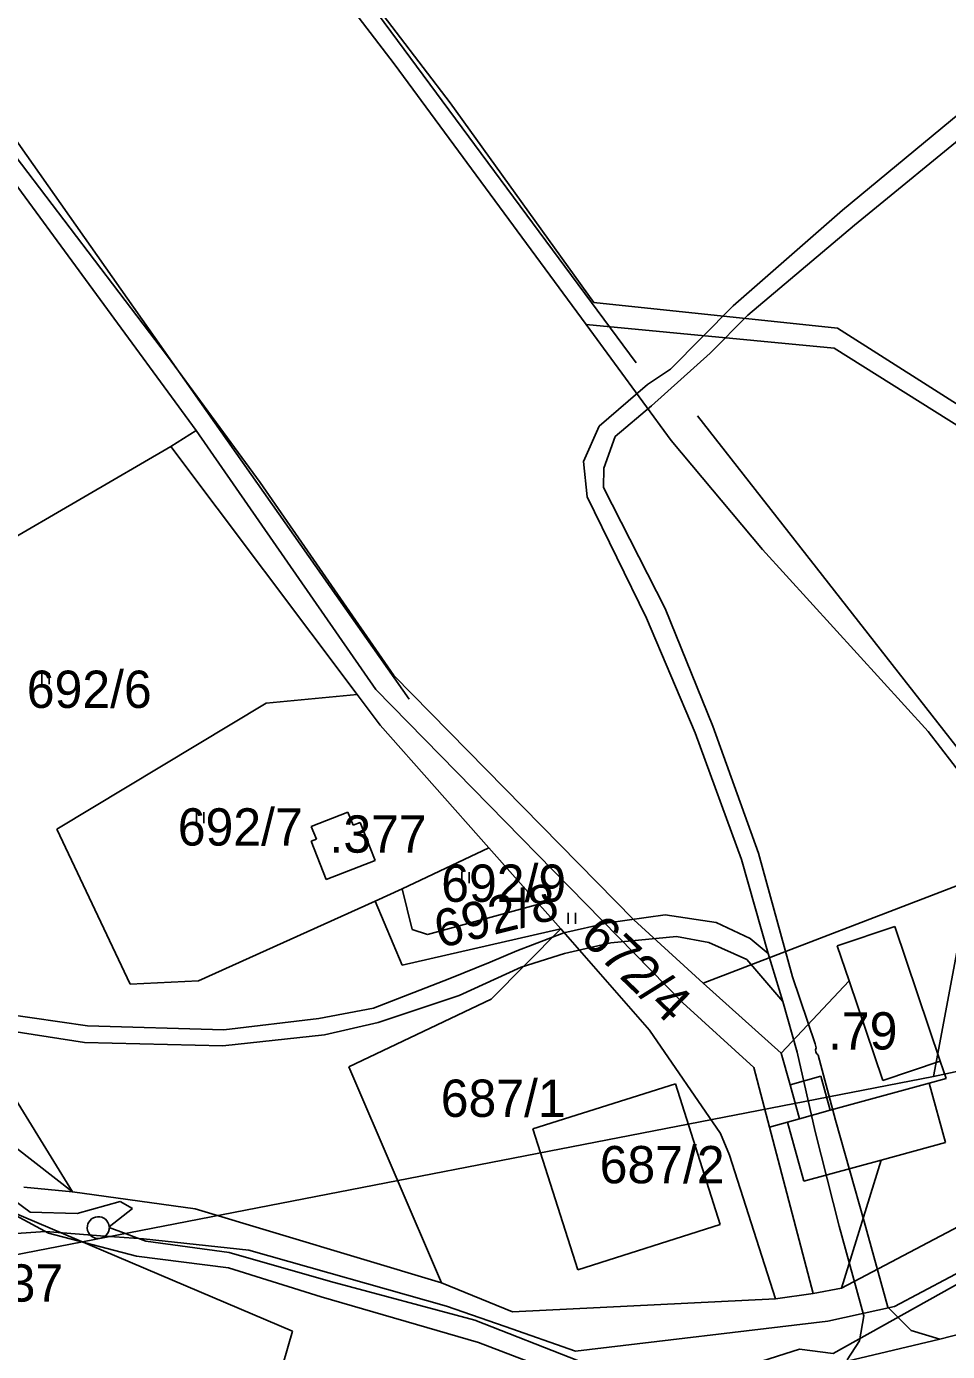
# Model space of a CAD drawing. Extents: x -564810 to -550519, y -1045831 to -1034011.
# Drawn here: x -554291.4 to -554165.5, y -1037725.9 to -1037544.7 of the extents above; entities that cross this region are included whole.
import ezdxf

# ---------------------------------------------------------------- set-up
doc = ezdxf.new("R2010")
doc.units = 0
for name, color, linetype in [('Interakční prvky', 7, 'Continuous'), ('KN stav', 7, 'Continuous'), ('Obvod KPU', 7, 'Continuous'), ('Parcelní čísla', 7, 'Continuous'), ('Polní cesty stavající', 7, 'Continuous'), ('STG', 7, 'Continuous'), ('Vedení VN', 7, 'Continuous'), ('Vrstva 22', 7, 'Continuous'), ('Vrstva 39', 7, 'Continuous'), ('Vrstva 4', 7, 'Continuous'), ('zamokř ploch', 7, 'Continuous')]:
    doc.layers.add(name, color=color, linetype=linetype)

msp = doc.modelspace()

# ---------------------------------------------------------------- linework, layer by layer
at = {"layer": 'Interakční prvky'}
for p, q in [((-554317.66, -1037442.66), (-554208.04, -1037590.75)), ((-554239.07, -1037636.71), (-554300.33, -1037549.62)), ((-554199.7, -1037597.96), (-554137.23, -1037677.8))]:
    msp.add_line(p, q, dxfattribs=at)
at = {"layer": 'KN stav'}
for p, q in [((-554233.47, -1037555.2), (-554266.14, -1037512.41)), ((-554259.35, -1037525.99), (-554241.13, -1037549.85)), ((-554241.13, -1037549.85), (-554214.89, -1037585.48)), ((-554302.81, -1037552.71), (-554268.19, -1037599.99)), ((-554272.12, -1037589.81), (-554298.22, -1037555.55)), ((-554213.84, -1037582.49), (-554233.47, -1037555.2)), ((-554180.54, -1037585.99), (-554213.84, -1037582.49)), ((-554214.89, -1037585.48), (-554203.29, -1037601.33)), ((-554181, -1037588.73), (-554214.89, -1037585.48)), ((-554136.03, -1037614.37), (-554180.54, -1037585.99)), ((-554139.36, -1037614.91), (-554181, -1037588.73)), ((-554259.44, -1037607.07), (-554272.12, -1037589.81)), ((-554268.19, -1037599.99), (-554271.62, -1037602.17)), ((-554243.64, -1037635.4), (-554268.19, -1037599.99)), ((-554271.62, -1037602.17), (-554327.63, -1037634.79)), ((-554271.62, -1037602.17), (-554246.18, -1037636.08)), ((-554203.29, -1037601.33), (-554190.8, -1037616.25)), ((-554241.16, -1037633.49), (-554259.44, -1037607.07)), ((-554190.8, -1037616.25), (-554168.17, -1037641.14)), ((-554327.63, -1037634.79), (-554285.1, -1037704.08)), ((-554208.37, -1037666.9), (-554241.16, -1037633.49)), ((-554246.18, -1037636.08), (-554258.63, -1037637.25)), ((-554258.63, -1037637.25), (-554246.18, -1037636.08)), ((-554246.18, -1037636.08), (-554243.04, -1037640.26)), ((-554243.04, -1037640.26), (-554246.18, -1037636.08)), ((-554201.66, -1037678.21), (-554243.64, -1037635.4)), ((-554258.63, -1037637.25), (-554287.21, -1037654.47)), ((-554287.21, -1037654.47), (-554258.63, -1037637.25)), ((-554243.04, -1037640.26), (-554228.17, -1037657.03)), ((-554228.17, -1037657.03), (-554243.04, -1037640.26)), ((-554168.17, -1037641.14), (-554159.09, -1037652.94)), ((-554247.46, -1037652.14), (-554252.45, -1037654.1)), ((-554252.45, -1037654.1), (-554247.46, -1037652.14)), ((-554246.74, -1037653.96), (-554247.46, -1037652.14)), ((-554247.46, -1037652.14), (-554246.74, -1037653.96)), ((-554287.21, -1037654.47), (-554277.22, -1037675.68)), ((-554277.22, -1037675.68), (-554287.21, -1037654.47)), ((-554252.45, -1037654.1), (-554251.76, -1037655.85)), ((-554251.76, -1037655.85), (-554252.45, -1037654.1)), ((-554245.75, -1037653.57), (-554246.74, -1037653.96)), ((-554246.74, -1037653.96), (-554245.75, -1037653.57)), ((-554243.72, -1037658.76), (-554245.75, -1037653.57)), ((-554245.75, -1037653.57), (-554243.72, -1037658.76)), ((-554251.76, -1037655.85), (-554252.47, -1037656.12)), ((-554252.47, -1037656.12), (-554251.76, -1037655.85)), ((-554252.47, -1037656.12), (-554250.41, -1037661.38)), ((-554250.41, -1037661.38), (-554252.47, -1037656.12)), ((-554228.17, -1037657.03), (-554240.04, -1037662.62)), ((-554240.04, -1037662.62), (-554228.17, -1037657.03)), ((-554221.34, -1037664.74), (-554228.17, -1037657.03)), ((-554250.41, -1037661.38), (-554243.72, -1037658.76)), ((-554243.72, -1037658.76), (-554250.41, -1037661.38)), ((-554155.28, -1037658.76), (-554198.91, -1037675.54)), ((-554240.04, -1037662.62), (-554243.73, -1037664.31)), ((-554243.73, -1037664.31), (-554240.04, -1037662.62)), ((-554240.04, -1037662.62), (-554238.66, -1037668.18)), ((-554267.85, -1037675.22), (-554243.73, -1037664.31)), ((-554243.73, -1037664.31), (-554267.85, -1037675.22)), ((-554243.73, -1037664.31), (-554240.04, -1037673.07)), ((-554236.56, -1037668.89), (-554221.34, -1037664.74)), ((-554220.84, -1037665.3), (-554221.34, -1037664.74)), ((-554218.34, -1037668.12), (-554220.84, -1037665.3)), ((-554198.91, -1037675.54), (-554208.37, -1037666.9)), ((-554240.04, -1037673.07), (-554218.34, -1037668.12)), ((-554238.66, -1037668.18), (-554236.56, -1037668.89)), ((-554218.34, -1037668.12), (-554227.87, -1037677.72)), ((-554227.87, -1037677.72), (-554218.34, -1037668.12)), ((-554206.23, -1037681.98), (-554218.34, -1037668.12)), ((-554218.34, -1037668.12), (-554206.23, -1037681.98)), ((-554172.72, -1037667.78), (-554180.58, -1037670.44)), ((-554166.5, -1037686.2), (-554172.72, -1037667.78)), ((-554180.58, -1037670.44), (-554178.97, -1037675.21)), ((-554277.22, -1037675.68), (-554267.85, -1037675.22)), ((-554267.85, -1037675.22), (-554277.22, -1037675.68)), ((-554198.91, -1037675.54), (-554188.23, -1037685.1)), ((-554178.97, -1037675.21), (-554188.23, -1037685.1)), ((-554227.87, -1037677.72), (-554247.33, -1037686.99)), ((-554247.33, -1037686.99), (-554227.87, -1037677.72)), ((-554192, -1037687.07), (-554201.66, -1037678.21)), ((-554196.53, -1037696.09), (-554206.23, -1037681.98)), ((-554206.23, -1037681.98), (-554196.53, -1037696.09)), ((-554188.23, -1037685.1), (-554187.03, -1037689.43)), ((-554247.33, -1037686.99), (-554234.67, -1037716.5)), ((-554234.67, -1037716.5), (-554247.33, -1037686.99)), ((-554189.86, -1037695.22), (-554192, -1037687.07)), ((-554165.7, -1037688.56), (-554166.5, -1037686.2)), ((-554168.04, -1037689.2), (-554165.7, -1037688.56)), ((-554202.69, -1037689.28), (-554222.16, -1037695.46)), ((-554222.16, -1037695.46), (-554202.69, -1037689.28)), ((-554196.57, -1037708.54), (-554202.69, -1037689.28)), ((-554202.69, -1037689.28), (-554196.57, -1037708.54)), ((-554187.03, -1037689.43), (-554185.75, -1037694.08)), ((-554165.8, -1037697.3), (-554168.04, -1037689.2)), ((-554187.39, -1037694.54), (-554189.86, -1037695.22)), ((-554185.75, -1037694.08), (-554187.39, -1037694.54)), ((-554179.99, -1037717.25), (-554136.29, -1037694.16)), ((-554136.29, -1037694.16), (-554179.99, -1037717.25)), ((-554295.91, -1037695.62), (-554285.1, -1037704.08)), ((-554222.16, -1037695.46), (-554216.04, -1037714.73)), ((-554216.04, -1037714.73), (-554222.16, -1037695.46)), ((-554195.31, -1037699.04), (-554196.53, -1037696.09)), ((-554196.53, -1037696.09), (-554195.31, -1037699.04)), ((-554189.86, -1037695.22), (-554183.88, -1037717.96)), ((-554174.58, -1037699.72), (-554165.8, -1037697.3)), ((-554189.02, -1037718.68), (-554195.31, -1037699.04)), ((-554195.31, -1037699.04), (-554189.02, -1037718.68)), ((-554179.99, -1037717.25), (-554174.58, -1037699.72)), ((-554291.75, -1037703.43), (-554285.1, -1037704.08)), ((-554285.1, -1037704.08), (-554291.75, -1037703.43)), ((-554255, -1037723.1), (-554299.71, -1037704.12)), ((-554299.71, -1037704.12), (-554255, -1037723.1)), ((-554285.1, -1037704.08), (-554268.32, -1037706.37)), ((-554268.32, -1037706.37), (-554285.1, -1037704.08)), ((-554268.32, -1037706.37), (-554234.67, -1037716.5)), ((-554234.67, -1037716.5), (-554268.32, -1037706.37)), ((-554216.04, -1037714.73), (-554196.57, -1037708.54)), ((-554196.57, -1037708.54), (-554216.04, -1037714.73)), ((-554234.67, -1037716.5), (-554224.94, -1037720.48)), ((-554224.94, -1037720.48), (-554234.67, -1037716.5)), ((-554189.02, -1037718.68), (-554183.88, -1037717.96)), ((-554183.88, -1037717.96), (-554189.02, -1037718.68)), ((-554183.88, -1037717.96), (-554179.99, -1037717.25)), ((-554179.99, -1037717.25), (-554183.88, -1037717.96)), ((-554224.94, -1037720.48), (-554189.02, -1037718.68)), ((-554189.02, -1037718.68), (-554224.94, -1037720.48)), ((-554256.98, -1037729.92), (-554255, -1037723.1)), ((-554255, -1037723.1), (-554256.98, -1037729.92))]:
    msp.add_line(p, q, dxfattribs=at)
at = {"layer": 'Obvod KPU'}
for p, q in [((-554172.78, -1037719.73), (-554130.68, -1037697.43)), ((-554337.84, -1037712.64), (-554288.75, -1037709.51)), ((-554288.75, -1037709.51), (-554280.66, -1037710.11)), ((-554280.66, -1037710.11), (-554275.36, -1037710.5)), ((-554275.36, -1037710.5), (-554260.99, -1037712.04)), ((-554260.99, -1037712.04), (-554233.97, -1037719.71)), ((-554233.97, -1037719.71), (-554225.94, -1037722.49)), ((-554181.85, -1037721.74), (-554172.78, -1037719.73)), ((-554216.33, -1037725.87), (-554181.85, -1037721.74)), ((-554225.94, -1037722.49), (-554216.33, -1037725.87))]:
    msp.add_line(p, q, dxfattribs=at)
at = {"layer": 'Polní cesty stavající'}
for p, q in [((-554152.74, -1037547.4), (-554179.85, -1037569.86)), ((-554178.23, -1037571.93), (-554151.36, -1037549.89)), ((-554179.85, -1037569.86), (-554194.8, -1037582.96)), ((-554192.81, -1037584.2), (-554178.23, -1037571.93)), ((-554194.8, -1037582.96), (-554203.36, -1037591.61)), ((-554197.96, -1037589.39), (-554192.81, -1037584.2)), ((-554205.97, -1037596.59), (-554197.96, -1037589.39)), ((-554203.36, -1037591.61), (-554206.49, -1037593.71)), ((-554206.49, -1037593.71), (-554213.12, -1037599.41)), ((-554210.93, -1037600.82), (-554205.97, -1037596.59)), ((-554213.12, -1037599.41), (-554215.27, -1037604.24)), ((-554212.46, -1037605.11), (-554210.93, -1037600.82)), ((-554215.27, -1037604.24), (-554214.76, -1037609.07)), ((-554212.5, -1037607.76), (-554212.46, -1037605.11)), ((-554214.76, -1037609.07), (-554206.66, -1037625.65)), ((-554204.08, -1037624.33), (-554212.5, -1037607.76)), ((-554206.66, -1037625.65), (-554200.01, -1037641.3)), ((-554197.57, -1037640.42), (-554204.08, -1037624.33)), ((-554200.01, -1037641.3), (-554193.65, -1037658.64)), ((-554191.35, -1037657.77), (-554197.57, -1037640.42)), ((-554186.7, -1037674.68), (-554191.35, -1037657.77)), ((-554193.65, -1037658.64), (-554190.03, -1037671.47)), ((-554211.9, -1037667.28), (-554217.92, -1037668.65)), ((-554204.1, -1037666.18), (-554211.9, -1037667.28)), ((-554197.12, -1037667.25), (-554204.1, -1037666.18)), ((-554192.46, -1037669.41), (-554197.12, -1037667.25)), ((-554217.92, -1037668.65), (-554224.35, -1037671.1)), ((-554211.5, -1037670.03), (-554202.53, -1037669.15)), ((-554202.53, -1037669.15), (-554198.15, -1037669.97)), ((-554217.85, -1037671.5), (-554211.5, -1037670.03)), ((-554198.15, -1037669.97), (-554192.94, -1037672.32)), ((-554190.03, -1037671.47), (-554192.46, -1037669.41)), ((-554228.01, -1037672.69), (-554233.54, -1037674.89)), ((-554224.35, -1037671.1), (-554228.01, -1037672.69)), ((-554223.79, -1037673.36), (-554217.85, -1037671.5)), ((-554192.94, -1037672.32), (-554188.04, -1037678.05)), ((-554190.03, -1037671.47), (-554188.04, -1037678.05)), ((-554190.03, -1037671.47), (-554188.04, -1037678.05)), ((-554188.04, -1037678.05), (-554190.03, -1037671.47)), ((-554232.26, -1037677.22), (-554223.79, -1037673.36)), ((-554183.6, -1037683.84), (-554186.7, -1037674.68)), ((-554233.54, -1037674.89), (-554243.95, -1037678.95)), ((-554243.33, -1037680.92), (-554232.26, -1037677.22)), ((-554188.04, -1037678.05), (-554186.05, -1037684.98)), ((-554283.02, -1037681.36), (-554294.38, -1037679.72)), ((-554243.95, -1037678.95), (-554251.4, -1037680.37)), ((-554303.2, -1037680.56), (-554283.44, -1037683.64)), ((-554264.41, -1037681.94), (-554283.02, -1037681.36)), ((-554251.4, -1037680.37), (-554264.41, -1037681.94)), ((-554250.66, -1037682.6), (-554243.33, -1037680.92)), ((-554283.44, -1037683.64), (-554264.52, -1037684.12)), ((-554264.52, -1037684.12), (-554250.66, -1037682.6)), ((-554186.05, -1037684.98), (-554183.59, -1037695.82)), ((-554183.46, -1037684.36), (-554183.6, -1037683.84)), ((-554180.83, -1037694.27), (-554183.2, -1037685.36)), ((-554290.87, -1037706.84), (-554310.28, -1037692.55)), ((-554176.89, -1037708.11), (-554180.83, -1037694.27)), ((-554183.59, -1037695.82), (-554180.31, -1037708.75)), ((-554278.58, -1037705.41), (-554284.45, -1037707.03)), ((-554276.87, -1037706.33), (-554278.58, -1037705.41)), ((-554294.49, -1037706.4), (-554288.38, -1037709.72)), ((-554284.45, -1037707.03), (-554290.87, -1037706.84)), ((-554280.07, -1037708.83), (-554276.87, -1037706.33)), ((-554275.07, -1037710.83), (-554280.06, -1037708.93)), ((-554180.31, -1037708.75), (-554176.97, -1037721.03)), ((-554173.68, -1037719.83), (-554176.89, -1037708.11)), ((-554288.38, -1037709.72), (-554276.35, -1037712.87)), ((-554263.67, -1037712.37), (-554275.07, -1037710.83)), ((-554249.84, -1037716.33), (-554263.67, -1037712.37)), ((-554276.35, -1037712.87), (-554263.77, -1037714.47)), ((-554263.77, -1037714.47), (-554251.09, -1037718.4)), ((-554230.1, -1037721.59), (-554249.84, -1037716.33)), ((-554251.09, -1037718.4), (-554229.58, -1037724.66)), ((-554170.46, -1037723.02), (-554173.68, -1037719.83)), ((-554215.92, -1037727.17), (-554230.1, -1037721.59)), ((-554176.97, -1037721.03), (-554177.56, -1037724.42)), ((-554166.56, -1037724.2), (-554170.46, -1037723.02)), ((-554229.58, -1037724.66), (-554217.2, -1037729.4)), ((-554179.23, -1037727.22), (-554166.56, -1037724.2)), ((-554177.56, -1037724.42), (-554179.23, -1037727.03))]:
    msp.add_line(p, q, dxfattribs=at)
for centre, radius, start, end in [((-554182.8, -1037684.72), 0.75, 151.7392, 238.0074), ((-554281.56, -1037708.96), 1.5, 4.8316, 0.9891)]:
    msp.add_arc(centre, radius, start, end, dxfattribs=at)
at = {"layer": 'STG'}
for points in [[(-554167.41, -1037688.29), (-554156.39, -1037629.49), (-554145.36, -1037590.9), (-554110.46, -1037535.77), (-554075.55, -1037487.99), (-554048, -1037440.22), (-554044.32, -1037364.87), (-554062.69, -1037282.18), (-554108.62, -1037205), (-554132.5, -1037168.25), (-554167.41, -1037129.66), (-554198.64, -1037089.24), (-554217.01, -1037052.48), (-554226.19, -1036964.28), (-554250.08, -1036927.53), (-554318.05, -1036929.37), (-554393.37, -1036945.9)], [(-553755.9, -1037388.76), (-553770.59, -1037447.57), (-553770.59, -1037486.16), (-553811.01, -1037524.75), (-553882.66, -1037574.36), (-553954.3, -1037625.81), (-553980.02, -1037635), (-554031.46, -1037658.89), (-554167.41, -1037688.29), (-554299.68, -1037714.02), (-554404.39, -1037728.72), (-554477.88, -1037741.58), (-554523.8, -1037756.28), (-554578.92, -1037787.52), (-554611.99, -1037848.16), (-554634.03, -1037903.29), (-554661.59, -1037958.42), (-554678.12, -1037969.44), (-554718.54, -1038002.52), (-554762.63, -1038019.06), (-554880.2, -1038048.46), (-554951.85, -1038055.81), (-555038.19, -1038074.19)]]:
    msp.add_lwpolyline(points, dxfattribs=at)
at = {"layer": 'Vedení VN'}
msp.add_lwpolyline([(-554145.43, -1037706.22), (-554181.13, -1037726.15), (-554185.72, -1037725.56), (-554227.93, -1037739.01), (-554276.86, -1037736.66)], dxfattribs=at)
at = {"layer": 'Vrstva 39'}
for p, q in [((-554161.02, -1037722.8), (-554166.56, -1037724.2)), ((-554166.56, -1037724.2), (-554179.23, -1037727.22))]:
    msp.add_line(p, q, dxfattribs=at)
at = {"layer": 'Vrstva 4'}
for p, q in [((-554174.36, -1037688.85), (-554178.97, -1037675.2)), ((-554166.5, -1037686.2), (-554174.36, -1037688.85)), ((-554182.83, -1037688.27), (-554187.03, -1037689.43)), ((-554181.55, -1037692.92), (-554182.83, -1037688.27)), ((-554168.04, -1037689.2), (-554181.55, -1037692.92)), ((-554187.39, -1037694.53), (-554185.16, -1037702.63)), ((-554181.55, -1037692.92), (-554185.75, -1037694.08)), ((-554174.58, -1037699.72), (-554185.16, -1037702.63))]:
    msp.add_line(p, q, dxfattribs=at)
at = {"layer": 'zamokř ploch'}
for p, q in [((-554289.26, -1037633.18), (-554289.26, -1037634.68)), ((-554288.26, -1037633.18), (-554288.26, -1037634.68)), ((-554268.14, -1037652.18), (-554268.14, -1037653.68)), ((-554267.14, -1037652.18), (-554267.14, -1037653.68)), ((-554231.88, -1037660.35), (-554231.88, -1037661.85)), ((-554230.88, -1037660.35), (-554230.88, -1037661.85)), ((-554217.36, -1037665.92), (-554217.36, -1037667.42)), ((-554216.36, -1037665.92), (-554216.36, -1037667.42))]:
    msp.add_line(p, q, dxfattribs=at)

# ---------------------------------------------------------------- texts
at = {"layer": 'Parcelní čísla'}
for s, p in [('692/6', (-554291.32, -1037637.91)), ('692/7', (-554270.69, -1037656.73)), ('692/9', (-554234.69, -1037664.42)), ('687/1', (-554234.76, -1037693.82)), ('687/2', (-554213.04, -1037702.9)), ('737', (-554297.74, -1037719.08))]:
    msp.add_text(s, height=5.1, dxfattribs=at).set_placement(p)
for s, rotation, p in [('692/8', 14.0925, (-554234.88, -1037670.79)), ('672/4', 316.1558, (-554215.95, -1037669.44))]:
    msp.add_text(s, height=5.1, rotation=rotation, dxfattribs=at).set_placement(p)
at = {"layer": 'Vrstva 22'}
for s, p in [('.377', (-554249.96, -1037657.7)), ('.79', (-554181.84, -1037684.61))]:
    msp.add_text(s, height=5.1, dxfattribs=at).set_placement(p)

doc.saveas('drawing.dxf')
